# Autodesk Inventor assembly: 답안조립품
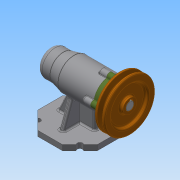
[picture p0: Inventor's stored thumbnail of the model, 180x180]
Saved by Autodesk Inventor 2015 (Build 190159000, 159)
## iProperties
Created: 2019-12
Part Number: 답안조립품
Document SubType Name: Assembly
Designer: user
Author: user
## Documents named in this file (12)
- C:\Users\user\Desktop\491204V1015\답안조립품.iam
- C:\Users\user\Desktop\491204V1015\본체.ipt
- C:\Users\user\Desktop\491204V1015\베어링 51202.ipt
- C:\Users\user\Desktop\491204V1015\어댑터슬리브.ipt
- C:\Users\user\Desktop\491204V1015\축.ipt
- C:\Users\user\Desktop\491204V1015\베어링 6004.ipt
- C:\Users\user\Desktop\491204V1015\볼트 M4.ipt
- C:\Users\user\Desktop\491204V1015\커버.ipt
- C:\Users\user\Desktop\491204V1015\오일 실.ipt
- C:\Users\user\Desktop\491204V1015\키 5 x 5 x 16.ipt
- C:\Users\user\Desktop\491204V1015\V벨트풀리.ipt
- C:\Users\user\Desktop\491204V1015\멈춤나사 M3.ipt
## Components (1 placed, 1 different names)
1. V벨트풀리:1
